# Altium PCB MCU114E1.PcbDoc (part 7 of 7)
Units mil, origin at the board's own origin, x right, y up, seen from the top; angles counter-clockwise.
Board outline 4163.97 x 2322.49 mil, 8 copper layers (Top Layer, GND 2, Signal Layer 3, Power 4, Power 5, Signal Layer 6, GND 7, Bottom), stack 61.2 mil thick; 444 components, 416 nets, 1812 pads, 989 vias.
Unrouted connection lines stored in the file: 3.
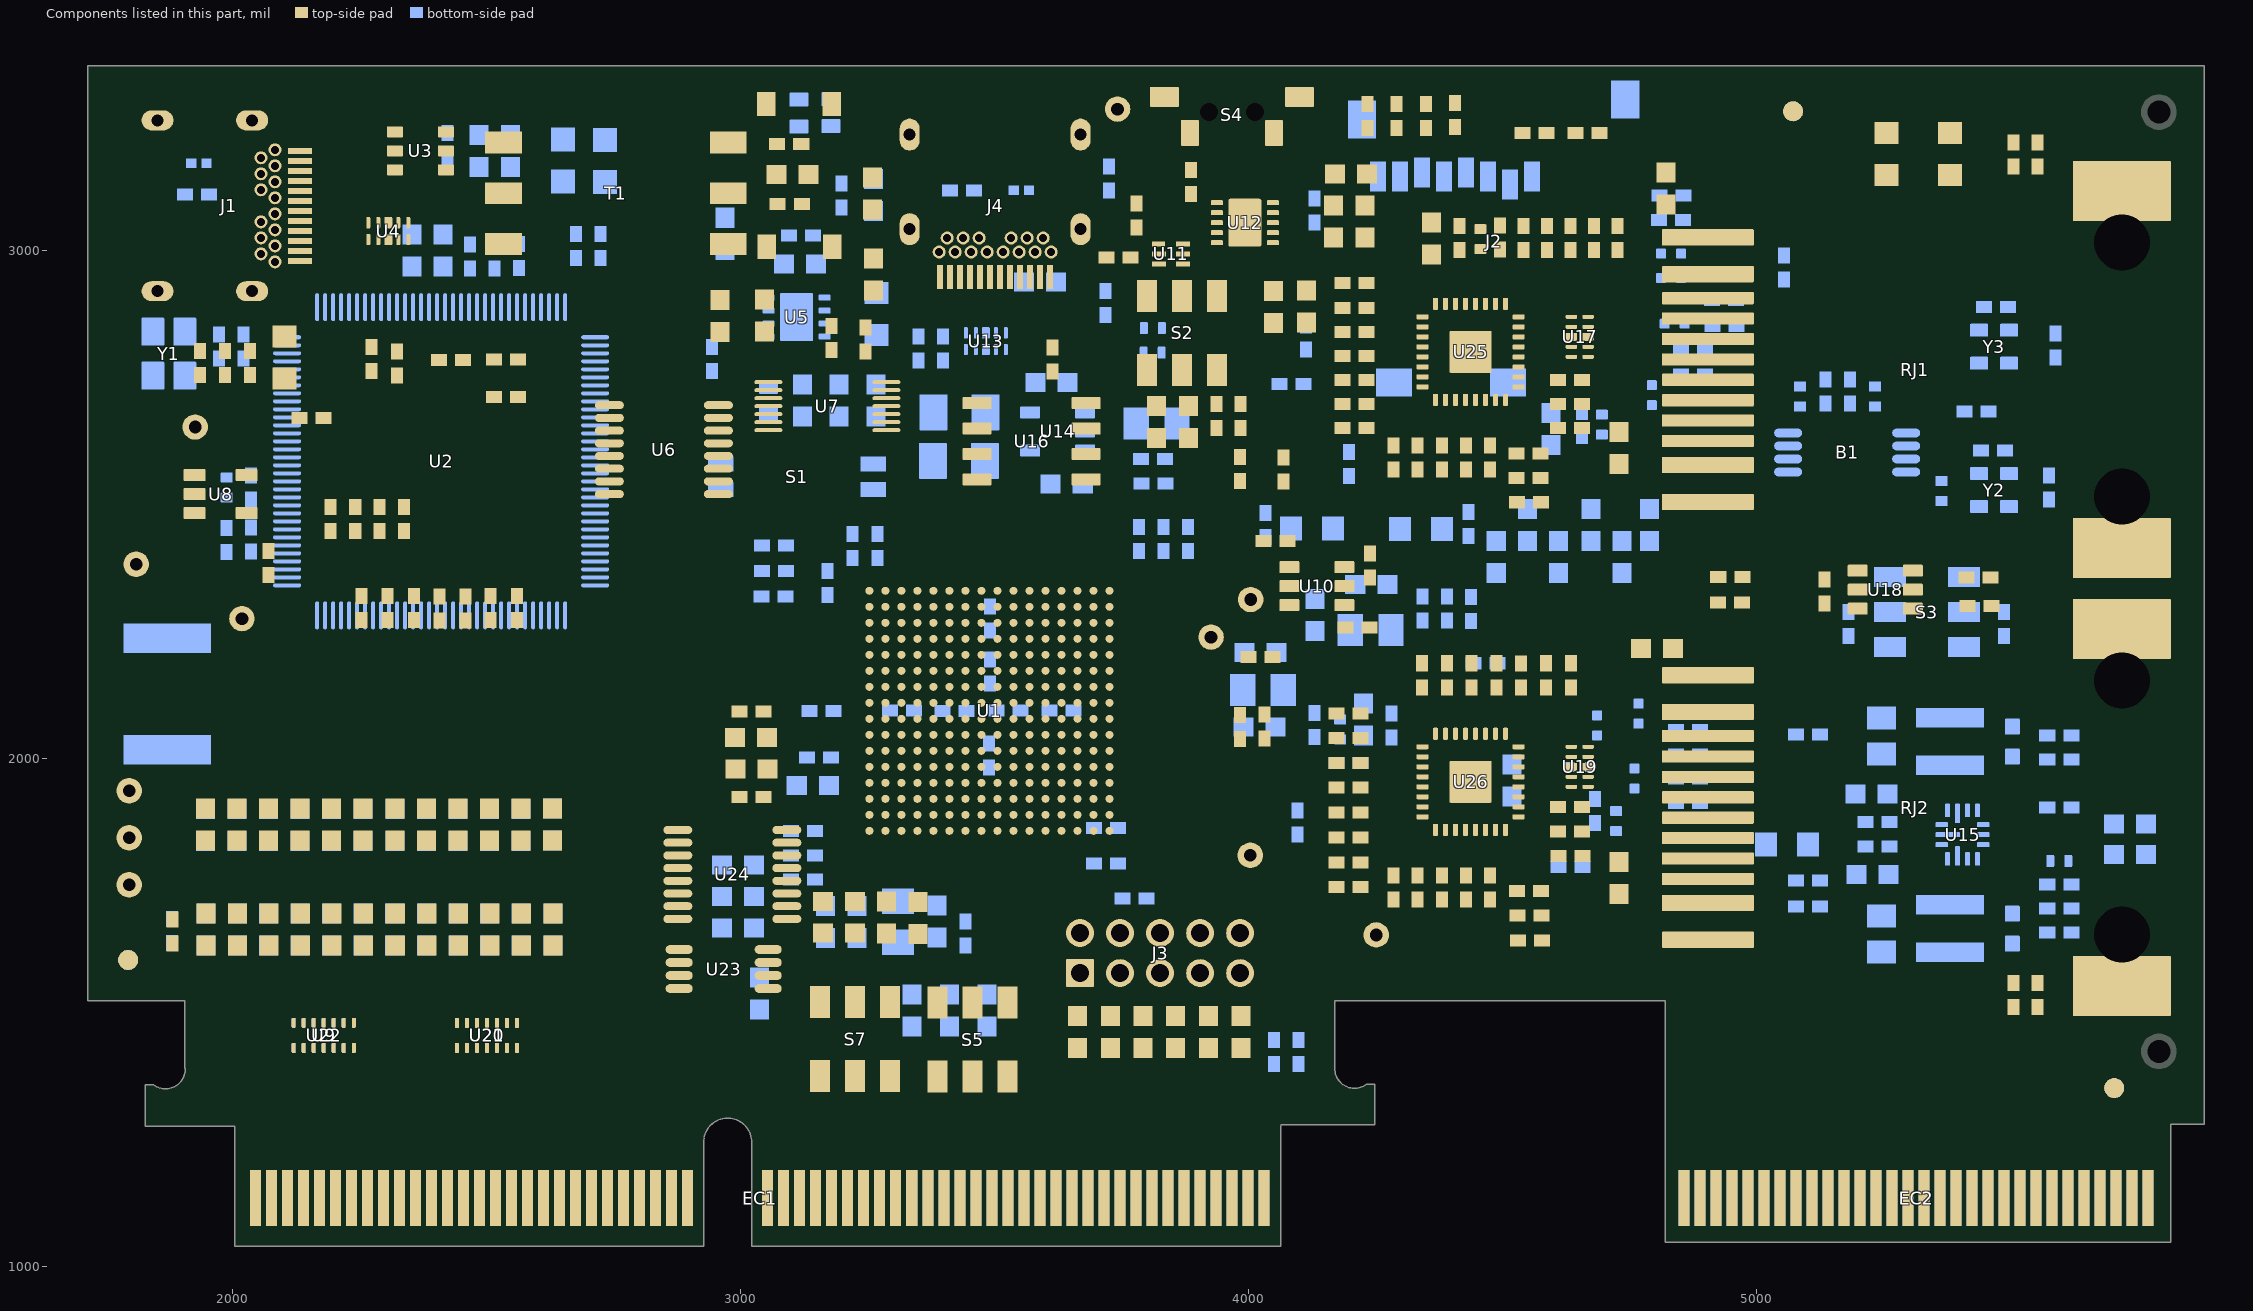
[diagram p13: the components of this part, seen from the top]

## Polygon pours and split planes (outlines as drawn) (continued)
NetC50_2 on Bottom "BOTTOM_NETC50_2_P194" (solid, remove dead copper, pour order 194): 5110,2069.34 5110,2013.68 5140.32,2013.68 5189.18,1964.82 5295.41,1964.82 5295.41,2025 5546,2025 5546,2058.05 5550.44,2062.5 5591.94,2062.5 5591.94,2028.87 5599.66,2028.87 5639.18,2028.87 5639.18,2106.82 5626,2120 5295.41,2120 5295.41,2054.66 5198.34,2054.66 5183.66,2069.34
NetL2_1 on Bottom "BOTTOM_NETL2_1_P219" (solid, remove dead copper, pour order 219): 5480,1958 5452.75,1958 5404.44,1909.69 5404.44,1871.16 5383.69,1871.16 5383.69,1932.72 5358.41,1958 5301,1958 5301,2026 5480,2026
NetL1_1 on Bottom "BOTTOM_NETL1_1_P222" (solid, remove dead copper, pour order 222): 5300,1744.71 5361.76,1744.71 5386,1768.96 5386,1828 5397.51,1828 5397.76,1828.24 5402.57,1823.43 5402.57,1788.43 5446.29,1744.71 5464,1744.71 5464,1676 5300,1676
5V0 on Bottom "BOTTOM_5V0_P225" (solid, remove dead copper, pour order 225): 5183.99,1801.23 5183.99,1844.5 5244,1844.5 5244,1820.73 5353.46,1820.73 5381.67,1820.73 5381.67,1764.63 5356.18,1739.14 5183.99,1739.14
5V0 on Bottom "BOTTOM_5V0_P229" (solid, remove dead copper, pour order 229): 5218.85,1959.23 5218.85,1896 5301,1896 5347,1896 5364.53,1878.47 5386.62,1878.47 5386.62,1946.38 5373.77,1959.23
5V0 on Bottom "BOTTOM_5V0_P230" (solid, remove dead copper, pour order 230): 5851.44,1971.69 5740.44,1971.69 5740.44,1851.69 5851.44,1851.69
EMU_USB_5V0 on Bottom "BOTTOM_EMU_USB_5V0_P231" (solid, remove dead copper, pour order 231): 2345.08,3216.85 2355.04,3216.85 2402.43,3216.85 2402.43,3207.9 2456.01,3207.9 2456.01,3189.27 2617.83,3189.27 2617.83,3074.27 2410.83,3074.27 2345.08,3140.02
5V0 on Bottom "BOTTOM_5V0_P232" (solid, remove dead copper, pour order 232): 3032.83,3339.27 3032.83,3271.27 3040.1,3264 3350,3264 3462.73,3151.27 3821.06,3151.27 3821.06,3339.27
EMU_3V3 on Bottom "BOTTOM_EMU_3V3_P234" (solid, remove dead copper, pour order 234): 2074.83,2690.27 2074.83,2542.27 1962.83,2542.27 1962.83,2690.27
EMU_GND on GND 2 "GND_2_EMU_GND_P206" (solid, remove dead copper, pour order 206): 1745.23,3346.77 2776.83,3346.77 2776.83,2365.27 2614.83,2203.27 1743.04,2203.27
ETH1_EARTH on GND 2 "GND_2_ETH1_EARTH_P172" (solid, remove dead copper, pour order 172): 5466,3228 5468,3230 5623,3230 5623,3332.84 5622.83,3333.01 5625.05,3335.23 5851.76,3335.23 5851.76,1337.49 5849.54,1335.27 5551.33,1335.27 5551.33,1598.1 5631.83,1598.1 5631.83,1728.84 5631.45,1729.22 5631.38,1729.16 4983.08,1729.16 4983.08,1806.03 5628.83,1806.03 5628.83,2186.78 5547.83,2267.78 5542.42,2267.78 5542.42,2430.79 5617.42,2505.79 5617.42,2593.86 5612.01,2599.27 4983.08,2599.27 4983.08,2696.27 5622.83,2696.27 5622.83,3075.27 5621.71,3074.15 5466.26,3074.15 5466.26,3229.26 5467,3230
GND on GND 2 "GND_2_GND_P227" (solid, remove dead copper, pour order 227): 1740.14,2050.63 1740.96,2051.46 2685.18,2051.46 2685.18,2053.82 2933.48,2302.12 2933.15,2302.46 2933.15,3360.09 5627.81,3355.97 5627.81,3074.15 5627.81,2694.47 4994.75,2694.47 4994.75,2597.93 5642.5,2597.93 5642.5,2517.86 5559.5,2434.86 5559.5,2266.44 5640.96,2184.98 5640.96,1817.39 5627.81,1804.23 4994.75,1804.23 4994.75,1727.82 5643.49,1727.82 5643.49,1593.18 5563.59,1593.18 5563.59,1545.84 5654.96,1454.47 5859.96,1454.47 5871.96,1442.47 5871.96,1304.47 5853.63,1286.13 5803.96,1286.13 5803.96,1061.47 4845.96,1061.47 4845.96,1504.75 4810.67,1540.04 4190.53,1540.04 4166.96,1516.47 4166.96,1366.47 4196.96,1336.47 4240.93,1336.47 4240.93,1286.13 4061.39,1286.13 4061.39,1055.47 3043.96,1055.47 3043.96,1260.36 3005.86,1298.47 2961.96,1298.47 2921.96,1258.47 2921.96,1062 2029.96,1061.47 2029.96,1280.49 1853.93,1280.49 1853.93,1309.44 1853.93,1340.47 1903.2,1340.47 1923.48,1360.75 1923.48,1540.04 1740.96,1538.47
EMU_GND on GND 7 "GND_7_EMU_GND_P189" (solid, remove dead copper, pour order 189): 1723.76,3352.27 2773.69,3352.27 2773.69,2361.12 2615.83,2203.27 1718.78,2203.27
GND on GND 7 "GND_7_GND_P223" (solid, remove dead copper, pour order 223): 1711.87,2049.75 2668.68,2049.75 2911.87,2292.93 2911.87,3339.75 5862.87,3339.75 5862.87,1399.27 5862.87,1283.27 5819.33,1283.27 5800.43,1264.37 5800.43,1034.29 4825.85,1034.29 4805.15,1054.99 4805.15,1508.27 4157.83,1508.27 4161.87,1504.23 4161.87,1363.27 4186.87,1343.27 4225.84,1343.27 4225.84,1274.29 4225.84,1264.37 4225.74,1264.27 4048.91,1264.27 4048.91,1030.29 4047.93,1031.27 3017.87,1031.27 3017.87,1243.12 2984.24,1276.75 2940.35,1276.75 2911.87,1248.27 2911.87,1042.27 2007.87,1042.27 2002.87,1037.27 2002.87,1269.27 1830.87,1269.27 1817.83,1282.31 1817.83,1342.27 1879.87,1342.27 1914.03,1376.43 1914.03,1535.75 1711.87,1535.75
VDDA_3V3 on Power 5 "POWER_5_VDDA_3V3_P176" (solid, remove dead copper, pour order 176): 1895.5,1554.5 1882,1568 1882,1949.33 1908.81,1976.14 2636.52,1976.14 2682.24,1930.41 2956.58,1930.41 2956.58,2068.27 3045.96,2157.65 3239.1,2157.65 3345.83,2050.92 3403.26,2050.92 3411.33,2042.86 3411.33,1987.27 3449.83,1948.77 3449.83,1911.66 3497.82,1863.66 3497.82,1649.78 3469.12,1621.08 3050.23,1621.08 3008.33,1579.17 3008.33,1292.33 2940.33,1292.33 2915.5,1267.5 2915.5,1063.5 2012.64,1063.5 2002.35,1073.79 2003.45,1074.89 2003.45,1280.06 1844.06,1280.06 1831.79,1292.33 1839.45,1299.99 1839.45,1350.61 1913.34,1350.61 1914.03,1351.3 1913.34,1550
VBUS_5V0 on Power 5 "POWER_5_VBUS_5V0_P207" (solid, remove dead copper, pour order 207): 3360.28,3165.77 3742.83,3165.77 3742.83,2775.28 3742.77,2775.34 3595.83,2775.34 3595.83,2695.9 3594.77,2694.83 3594.94,2694.66 3683.46,2694.66 3683.46,2516.61 3682.8,2517.27 3366.15,2517.27
ISO_Pout_5V0 on Power 5 "POWER_5_ISO_POUT_5V0_P218" (solid, remove dead copper, pour order 218): 2925.35,2938.68 3006.12,2938.68 3006.12,2816.64 3177.72,2816.64 3177.72,3106.79 3226.83,3155.9 3226.83,3332.27 2925.09,3332.27 2924.35,3333.01
EMU_3V3 on Power 5 "POWER_5_EMU_3V3_P228" (solid, remove dead copper, pour order 228): 1737.26,3345.27 2781.99,3345.27 2781.99,2369.43 2613.83,2201.27 1732.3,2201.27
3V3 on Power 5 "POWER_5_3V3_P246" (solid, remove dead copper, pour order 246): 1724.35,2052.27 2679.08,2052.27 2916.26,2300.45 2920.95,3363.27 5875.35,3363.27 5875.35,1422.79 5875.35,1306.79 5831.81,1306.79 5812.91,1287.89 5812.91,1057.81 4838.33,1057.81 4817.63,1078.51 4817.63,1531.79 4170.32,1531.79 4174.35,1527.75 4174.35,1386.79 4199.35,1366.79 4238.32,1366.79 4238.32,1297.81 4238.32,1287.89 4238.22,1287.79 4061.39,1287.79 4061.39,1053.81 4060.42,1054.79 3030.35,1054.79 3030.35,1266.64 2996.72,1300.27 2952.83,1300.27 2924.35,1271.79 2924.35,1060.79 2015.35,1060.79 2002.35,1073.79 2002.35,1292.79 1843.35,1292.79 1830.32,1305.83 1830.32,1365.79 1892.35,1365.79 1914.35,1387.79 1914.35,1541.79 1724.35,1541.79

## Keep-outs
Keep-Out Layer:
  text ".Layer_Name" at -765.05,-899.49 h60

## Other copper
Top Layer:
  pour cut-out: 3998.12,1341.27 4008,1331.39 4008,1330 4077,1399 4064,1412 4064,1407.15
  pour cut-out: 2035.26,1075.15 2897.18,1075.15 2897.18,1071.04 2035.26,1071.04
  pour cut-out: 3052.19,1075.15 4036.15,1075.15 4032.62,1071.62 4032.62,1071.04 3052.19,1071.04
  pour cut-out: 3816.28,1803 3823.96,1803 3824.37,1803.42 3916.79,1711 3912.19,1711 3902.4,1701.21 3815.51,1788.09 3815.51,1801.15
  pour cut-out: 3264.59,1929.58 3264.59,1924.78 3286.84,1902.53 3272.61,1888.29 3239.44,1888.29 3231.94,1895.78 3264.51,1928.35
  pour cut-out: 3390.41,1878.36 3422.28,1878.36 3426.45,1874.19 3420.14,1867.88 3420.14,1812.39 3399.98,1812.39 3390.41,1821.95
  pour cut-out: 3360.96,1947.64 3367.56,1947.64 3411.33,1947.64 3411.33,1873.75 3411.33,1878.36 3401.09,1878.36 3361.06,1878.36 3361.05,1887.28 3360.96,1942
  pour cut-out: 3476.63,2059.92 3482.38,2065.66 3503.01,2065.66 3503.01,1798.5 3496.8,1792.3 3494.41,1794.68 3479,1794.68 3479,1860.24 3462.72,1876.52 3460.39,1874.19 3434.05,1874.19 3434.05,1929.62 3467.44,1963.01 3467.44,2054.98 3472.38,2059.92
  pour cut-out: 3520.86,2107.12 3738.77,2107.12 3738.77,2086.67 3739.25,2086.19 3738.59,2085.52 3513.76,2085.52 3513.76,2100.03
  pour cut-out: 3471.51,2317.63 3508.13,2317.63 3508.13,2194.55 3502.35,2188.77 3502.11,2189.02 3442.82,2189.02 3442.82,2294.84 3467.34,2319.36
  pour cut-out: 2903,2732 2906.48,2728.52 2924.45,2728.52 2924.45,2541.46 2923.64,2540.66 2918.31,2546 2901,2546 2901,2730
  pour cut-out: 3894,2334 3900.17,2327.83 3945.77,2327.83 3945.77,2305.21 3931.83,2291.27 3928.06,2295.04 3854.17,2295.04 3854.17,2303.35 3885.86,2335.04
  text ".Layer_Name" at -733,-894 h60
Signal Layer 3:
  text ".Layer_Name" at -777.17,-912.73 h60
GND 2:
  text ".Layer_Name" at -742.17,-892.73 h60
GND 7:
  text ".Layer_Name" at -737.17,-889.73 h60
Signal Layer 6:
  text ".Layer_Name" at -725.17,-888.73 h60
Power 4:
  text ".Layer_Name" at -713.17,-903.73 h60
Power 5:
  text ".Layer_Name" at -737.17,-889.73 h60
Bottom:
  pour cut-out: 5368.98,1336.77 5372.08,1339.87 5388.48,1339.87 5388.48,1290.83 5390.44,1288.87 5381.76,1280.19 5371.77,1280.19 5371.77,1333.98
  pour cut-out: 5793,1238 5793,1196 5792.39,1195.39 5781.08,1195.39 5781.08,1228.92 5772,1238
  text ".Layer_Name" at -732.17,-905.73 h60

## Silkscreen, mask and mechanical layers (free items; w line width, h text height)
Top Overlay:
  text "-----------------------------" at 2900.19,3314.34 h35 r269.64
  text "---------------------------" at 2769.15,3308.34 h35 r269.64
  text "ETH1_EARTH" at 5508,3277.1 h40
  text "5V0" at 3716,3215.44 h40
  text "P0" at 4979,3161.78 h65
  text "XRSn" at 4008,3158.44 h40
  text "1" at 3982,2934.27 h40
  text "0" at 3735,2904.94 h40
  text "SEL 1" at 3651.49,2865.05 h40
  text "SEL 2" at 3651.49,2789.12 h40
  text "0" at 3730,2739.44 h40
  text "1" at 3983.6,2733.42 h40
  text "EMU_5V0" at 1951.54,2609.96 h40
  text "EMU_3V3" at 1754.67,2424.69 h40
  text "VDD_1V2" at 3805.04,2301.1 h40
  text "XRSn" at 3799,2226.44 h40
  text "EMU_GND" at 1928.9,2214.53 h40
  text "Cold Side" at 2619.69,2210.52 h55 r47.05
  text "-------" at 2626.55,2182.98 h35 r45.17
  text "------------------------" at 1772.83,2176.77 h35
  text "Hot Side" at 2772.82,2089.6 h55 r45.91
  text "----------" at 2688.55,2044.71 h35 r46.53
  text "--------------------------" at 1770.09,2037.49 h35
  text "HSEC_5V0" at 1728,1880.1 h40
  text "VDDIO_3V3" at 3768.34,1801.17 h40
  text "GND" at 1763.85,1788.79 h35
  text "3V3" at 1760,1695.44 h40
  text "ERRORSTS" at 4022,1637.44 h40
  text "SEL 1" at 3411.36,1564.69 h40
  text "SEL 2" at 3180.51,1560.71 h40
  text "1" at 3129,1559 h40
  text "0" at 3318.8,1558.4 h40
  text "0" at 3354.18,1558.29 h40
  text "1" at 3543,1558 h40
  text "Ext Vref" at 2978.27,1486.61 h40
  text "P1" at 4985.61,1482 h65
  text "ETH1_EARTH" at 5515,1415.1 h40
  text "1" at 3121,1310 h40
  text "0" at 3311.26,1309.38 h40
  text "0" at 3354.75,1308.61 h40
  text "SEL 1" at 3185.83,1307.93 h40
  text "SEL 2" at 3400,1304.44 h40
  text "1" at 3537.83,1304.45 h40
  text "55" at 2880,1280.94 h40
  text "57" at 3039,1280.94 h40
  text "119" at 3994,1280.71 h40
  text "121" at 4831,1280.71 h40
  text "179" at 5739,1280.71 h40
  text "1" at 2029.96,1280.49 h40
  text ".Layer_Name" at -752.17,-886.73 h60
Bottom Overlay:
  region: 4512,1714 4367,1714 4367,1649 4512,1649
  text "-----------------------------" at 2900.19,3314.34 h35 r269.64
  text "---------------------------" at 2769.15,3308.34 h35 r269.64
  text "0" at 2926.6,2621.15 h40
  text "1" at 3300,2602 h40
  text "SEL 1" at 3307.67,2569.14 h40 r270
  text "1" at 3298.95,2474.95 h40
  text "SEL 2" at 3308.77,2465.55 h40 r270
  text "0" at 2933,2464.44 h40
  text "1" at 5217.79,2389.18 h40
  text "1" at 5462.68,2383.61 h40
  text "SEL 2" at 5185,2370.44 h40
  text "SEL 1" at 5575,2367.44 h40
  text "-------" at 2626.55,2182.98 h35 r45.17
  text "0" at 5203.35,2176.87 h40
  text "------------------------" at 1771.83,2175.77 h35
  text "0" at 5447.95,2173.86 h40
  text "----------" at 2688.54,2044.71 h35 r46.5
  text "--------------------------" at 1770.09,2037.49 h35
  text "'.PRJ_Number'.PCB_Rev-" at 4814.67,1664.88 h60
  text "C2000 F28P65x controlCARD" at 5030,1595 h60
  text "2" at 2046.62,1282.29 h40
  text "56" at 2917,1281 h40
  text "58" at 3064.19,1281.3 h40
  text "120" at 4049,1281 h40
  text "122" at 4887.35,1279.94 h40
  text "180" at 5794,1280 h40
  text ".Layer_Name" at -750.17,-896.73 h60
Top Paste:
  text ".Layer_Name" at -765.05,-899.49 h60
Bottom Paste:
  text ".Layer_Name" at -765.05,-899.49 h60
Top Solder:
  rectangle: 4817,1044.63 5817,1241
  rectangle: 2002.01,1032 2932,1238.09
  rectangle: 3017.87,1035 4075,1241
  text ".Layer_Name" at -765.05,-899.49 h60
  text ".Layer_Name" at -765.05,-899.49 h60
Bottom Solder:
  rectangle: 4816,1037.81 5817,1240
  rectangle: 2002,1040.78 2927.44,1240.39
  rectangle: 3022.33,1040.78 4069,1239.79
  text ".Layer_Name" at -765.05,-899.49 h60
Drill Guide:
  text ".Layer_Name" at -765.05,-899.49 h60
M1 Board Outline:
  lines w10: 1906.8,1391.27 1906.8,1524.27 1715.83,1524.27 1715.83,3363.27 5877.8,3363.27 ; 1907.3,1391.29 cw(c1868.35,1389.36) 1844.8,1358.27 1828.8,1358.27 1828.8,1277 2005,1277 2005,1045.98 ; 2010.84,1041.04 2922.46,1041.04 ; 2927.26,1047.48 2927.26,1241.96 ; 2927.36,1242.93 cw(c2974.85,1242.55) 3022.33,1242.93 3022.33,1045.77 ; 3027.41,1040.69 4070.11,1040.76 ; 4070.11,1046.6 4070.11,1276.93 ; 4070.11,1280.27 4247.8,1280.27 4247.8,1359.27 4231.8,1359.27 cw(c4208.3,1390.39) 4169.3,1390.27 ; 4168.8,1390.27 4168.8,1487.86 4168.8,1524.27 4819.11,1524.27 4819.11,1048.27 5814.39,1048.27 5814.39,1280.37 5879.8,1280.37 5879.8,3363.27
  text ".Layer_Name" at -765.05,-899.49 h60
M2 Board Dimensions:
  rectangle: -1342.05,-315.99 -1217.05,-190.99
  rectangle: -1217.05,-440.99 -842.05,-315.99
  lines w5: 1998.81,1311.29 2008.81,1301.29 ; 2018.81,1311.29 2008.81,1301.29 ; 2178.81,1346.29 2033.81,1346.29 2008.81,1321.29 2008.81,1301.29 ; 4088.81,1251.29 4088.81,1266.29 ; 4103.81,1266.29 4088.81,1266.29 ; 4103.81,1561.29 4103.81,1526.29 4123.81,1526.29 4153.81,1526.29 ; 4143.81,1516.29 4153.81,1526.29 ; 4143.81,1536.29 4153.81,1526.29 ; 4338.81,1576.29 4348.81,1566.29 4823.81,1566.29 4823.81,1546.29 4823.81,1531.29 ; 4473.81,691.29 4473.81,861.29 4118.81,1216.29 4118.81,1236.29 4088.81,1266.29 ; 4813.81,1541.29 4823.81,1531.29 ; 4833.81,1541.29 4823.81,1531.29 ; 5778.81,1396.29 5778.81,1371.29 5798.81,1351.29 5818.81,1331.29 5818.81,1316.29 5818.81,1291.29 ; 5808.81,1301.29 5818.81,1291.29 ; 5828.81,1301.29 5818.81,1291.29
  lines w7: -1342.05,-315.99 -342.05,-315.99 ; -1217.05,-440.99 -1217.05,-190.99 ; -1092.05,-440.99 -1092.05,-190.99 ; -842.05,-440.99 -842.05,-190.99 ; -592.05,-440.99 -592.05,-190.99 ; -1342.05,-440.99 -342.05,-440.99 -342.05,-190.99 -1342.05,-190.99 -1342.05,-440.99
  lines w10: 1923.81,1566.29 1923.81,1546.29 ; 1943.81,1546.29 1923.81,1546.29 ; 2018.81,1561.29 1938.81,1561.29 1923.81,1546.29 ; 8495.95,186.01 8563.95,186.01 ; 8537.95,157.01 8564.95,185.01 ; 8537.95,216.01 8564.95,186.01 ; 8571.95,1531.01 8639.95,1613.01 ; 8573.95,139.01 8573.95,461.01 ; 8573.95,502.01 8623.95,448.01 8733.95,448.01 8780.95,505.01 ; 8573.95,504.01 8573.95,1534.01 ; 8638.95,1614.01 8702.95,1527.01 ; 8656.95,354.01 8724.95,354.01 ; 8698.95,325.01 8725.95,353.01 ; 8698.95,384.01 8725.95,354.01 ; 8703.95,1526.01 8775.95,1616.01 ; 8734.95,139.01 8734.95,421.01 ; 8780.95,504.01 8780.95,1534.01 8780.95,1619.01 ; 8781.95,139.01 8781.95,461.01 ; 8787.92,1154.63 cw(c8731.95,447.01) 9171.29,1004.54 ; 8789.8,1153.26 ccw(c8929.55,1387.92) 8840.67,1129.67 ; 8789.95,189.01 8816.95,159.01 ; 8789.95,190.01 8816.95,218.01 ; 8789.95,1160.01 cw(c8822.4,986.03) 8852.67,1160.4 ; 8791.95,190.01 8859.95,190.01 ; 8791.95,353.01 8818.95,323.01 ; 8791.95,354.01 8818.95,382.01 ; 8793.95,354.01 8861.95,354.01 ; 8807.95,543.01 9270.95,1115.01 ; 9117.95,1019.01 ccw(c9255.48,1359.44) 9172.61,1001.75 ; 9135.2,1052.31 cw(c9018.34,918.86) 9173.95,1004
  text "X2" at 4228.81,1681.29 h60
  text "R 39.00" at 4004.83,1593.27 h60
  text "R 39.00" at 2048.81,1541.29 h60
  text "R 39.00" at 5458.81,1416.29 h60
  text "R 39.00" at 2208.81,1311.29 h60
  text "30" at 8976.95,1175.01 h60
  text "R 39.00" at 4343.81,606.29 h60
  text "18MIL" at 8902.95,326.01 h60
  text "62MIL" at 8895.95,162.01 h60
  text "GOLD FINGER" at 8414.95,-74.99 h60
  text "SIDE VIEW" at 8468.95,-187.99 h60
  text ".Layer_Name" at -765.05,-899.49 h60
M3 3D STEP Top:
  text ".Layer_Name" at -765.05,-899.49 h60
M4 3D STEP Bottom:
  text ".Layer_Name" at -765.05,-899.49 h60
M5 Assembly Top:
  lines w10: -1634.05,-971.16 4965.95,-971.16 ; -1634.05,-767.83 4967.95,-767.83 ; -1634.05,-564.49 -1634.05,-1174.49 2370.95,-1174.49 4967.95,-1174.49 4967.95,-564.5 -1633.55,-564.5 -1633.55,-1174.49 -58.05,-1174.49 ; 830.95,-1174.49 830.95,-564.5 ; 2097.95,-767.83 2097.95,-564.5 ; 2937.95,-767.83 2937.95,-564.5 ; 3559.95,-1180.99 3559.95,-978.16
  text "COMPONENTS MARKED 'DNP' SHOULD NOT BE POPULATED." at -188.55,-359.49 h60
  text "ASSEMBLY VARIANT:" at -189.05,-474.99 h60
  text ".VariantName" at 846.95,-474.99 h60
  text "PCB VIEWED FROM TOP SIDE" at -1570.55,-696.66 h60
  text "BOARD #:" at 905.95,-696.66 h60
  text ".PRJ_Number" at 1451.45,-696.66 h60
  text "REV:" at 2295.95,-696.66 h60
  text ".PCB_Rev" at 2587.45,-696.66 h60
  text "SVN REV:" at 3133.95,-696.66 h60
  text "TID #:" at 905.95,-899.99 h60
  text ".TID" at 1451.45,-899.99 h60
  text "PLOT NAME =" at -1570.55,-1105.33 h60
  text ".plot_File_Name" at -765.05,-1105.33 h60
  text "GENERATED    :" at 907.95,-1105.33 h60
  text ".Print_Date" at 1777.45,-1105.33 h60
  text ".Print_Time" at 2506.45,-1105.33 h60
  text "TEXAS INSTRUMENTS" at 3770.95,-1105.33 h60
M6 Assembly Bottom:
  lines w10: -1634.55,-768.33 4967.45,-768.33 ; -1632.55,-971.66 4967.45,-971.66 ; -226.55,-1181.49 -226.55,-978.66 ; 395.45,-768.33 395.45,-565 ; 1235.45,-768.33 1235.45,-565 ; 2502.45,-1174.99 2502.45,-565 ; 3391.45,-1174.99 4966.95,-1174.99 4966.95,-564.99 -1634.55,-565 -1634.55,-1174.99 962.45,-1174.99 4967.45,-1174.99 4967.45,-564.99
  text "COMPONENTS MARKED 'DNP' SHOULD NOT BE POPULATED." at 4759.95,-358.99 h60
  text ".VariantName" at 3715.95,-474.99 h60
  text "ASSEMBLY VARIANT:" at 4754.95,-474.99 h60
  text "SVN REV:" at 199.45,-697.16 h60
  text ".PCB_Rev" at 745.95,-697.16 h60
  text "REV:" at 1037.45,-697.16 h60
  text ".PRJ_Number" at 1881.95,-697.16 h60
  text "BOARD #:" at 2427.45,-697.16 h60
  text ".TID" at 1881.95,-900.49 h60
  text "TID #:" at 2427.45,-900.49 h60
  text "TEXAS INSTRUMENTS" at -437.55,-1105.83 h60
  text ".Print_Time" at 826.95,-1105.83 h60
  text ".Print_Date" at 1555.95,-1105.83 h60
  text "GENERATED    :" at 2425.45,-1105.83 h60
  text ".plot_File_Name" at 4098.45,-1105.83 h60
  text "PLOT NAME =" at 4903.95,-1105.83 h60
M9 Title Sheet:
  drawing of 57 lines, arcs and shapes, not listed
  text "1" at -602.21,7995.51 h70
  text "2" at 1893.45,7995.51 h70
  text "3" at 4382.79,7995.51 h70
  text "4" at 6889.46,7995.51 h70
  text "5" at 9388.45,7995.51 h70
  text "6" at 11893.45,7995.51 h70
  text "A" at -1758.55,6852.51 h70
  text "A" at 13041.45,6852.51 h70
  text "B" at -1758.55,4472.51 h70
  text "B" at 13041.45,4472.51 h70
  text "C" at -1758.55,2097.51 h70
  text "C" at 13041.45,2097.51 h70
  text "PROJECT TITLE:" at 10001.45,236.51 h45
  text ".PRJ_Title" at 10051.45,103.18 h70
  text "DESIGNED FOR:" at 10001.45,-64.49 h45
  text ".PRJ_Customer" at 10051.45,-204.49 h70
  text "D" at -1758.55,-272.49 h70
  text "D" at 13041.45,-272.49 h70
  text "FILE NAME:" at 10001.45,-364.49 h45
  text ".PCB_File_Name_No_Path" at 10051.45,-484.49 h70
  text "Texas Instruments (TI) and/or its licensors do not warrant the accuracy or completeness of this specification" at 5031.95,-646.33 h45
  text "ENGINEER:" at 10001.45,-654.49 h45
  text "LAYOUT BY:" at 11506.45,-654.49 h45
  text "or any information contained therein. TI and/or its licensors do not warrant that this design will meet" at 4986.97,-759 h45
  text ".PRJ_Engineer" at 10051.45,-809.49 h70
  text ".PCB_Layout" at 11556.95,-809.49 h70
  text "the specifications, will be suitable for your application or fit for any particular purpose, or will operate in" at 4986.97,-871.66 h45
  text ".Layer_Name" at -765.05,-899.49 h60
  text "ALTIUM DESIGNER VERSION:" at 11506.45,-964.49 h45
  text "an implementation. TI and/or its licensors do not warrant that the design is production worthy. You should" at 4986.97,-984.33 h45
  text "completely validate and test your design implementation to confirm the system functionality for your application." at 5031.95,-1096.99 h45
  text ".print_Scale" at 10051.45,-1097.82 h70
  text ".Application_BuildNumber" at 11556.95,-1097.82 h70
  text "1" at -602.21,-1304.49 h70
  text "2" at 1893.45,-1304.49 h70
  text "3" at 4382.79,-1304.49 h70
  text "4" at 6889.46,-1304.49 h70
  text "5" at 9388.45,-1304.49 h70
  text "6" at 11893.45,-1304.49 h70
M10 Fab Notes:
  drawing of 185 lines, arcs and shapes, not listed
  text "DESIGN INFORMATION" at 11039.97,6455.18 h60
  text "5" at 11493.81,6326.29 h60
  text "MIN. TRACK WIDTH:" at 10395.41,6323.05 h60
  text "MIL" at 11646.41,6323.05 h60
  text "4" at 11503.81,6206.29 h60
  text "MIN. CLEARANCE:" at 10395.41,6198.93 h60
  text "MIL" at 11646.41,6198.93 h60
  text "MIN. VIA PAD SIZE:" at 10395.41,6074.8 h60
  text "18" at 11461.66,6074.8 h60
  text "MIL" at 11646.41,6074.8 h60
  text "0.05mm (2MIL)" at 11090.41,5944.9 h60
  text "MINIMUM ANNULAR RING" at 10066.18,5936.68 h60
  text "EXTERNAL" at 11798.41,5936.68 h60
  text "PER" at 10266.18,5826.55 h60
  text "IPC-D-275 CLASS 2 LEVEL C" at 10486.18,5826.55 h60
  text "MIL, HOLES" at 11974.41,5726.07 h60
  text "+/-" at 11581.95,5717.49 h60
  text "+/-" at 12435.95,5717.49 h60
  text "REGISTRATION TOLERANCES:" at 10066.18,5716.42 h60
  text "METAL" at 11265.95,5716.42 h60
  text "5" at 11842.15,5716.43 h60
  text "3" at 12675.15,5716.43 h60
  text "MIL" at 12791.41,5716.42 h60
  text "HOLE SIZE TOLERANCE (UNLESS OTHERWISE SPECIFIED):" at 10066.18,5618.11 h60
  text "+/-" at 12435.95,5615.24 h60
  text "3" at 12675.15,5614.17 h60
  text "MIL" at 12791.41,5614.17 h60
  text "MATERIAL:" at 9991.41,5476.52 h60
  text "FR-4 High Tg" at 10977.85,5348 h60
  text "X" at 10833.41,5340.01 h60
  text "FR-408" at 10412.41,5335.49 h60
  text "OTHER" at 11900.41,5335.49 h60
  text "62 MIL (1.57mm) +/-10%" at 10732.51,5192.46 h60
  text "X" at 10612.41,5190.01 h60
  text "THICKNESS:" at 10066.18,5184.24 h60
  text "OTHER" at 12017.41,5184.24 h60
  text "TOLERANCE:" at 10066.18,5045.93 h60
  text "X" at 10914.41,5045.93 h60
  text "ANSI IPC-6012 TYPE 3 CLASS 2" at 11092.43,5045.93 h60
  text "OTHER +/-" at 11092.41,4901.74 h60
  text "BOW & TWIST:" at 10066.18,4756.55 h60
  text "X" at 10914.41,4756.55 h60
  text "ANSI IPC-6012 TYPE 3 CLASS 2" at 11092.43,4756.55 h60
  text "OTHER +/-" at 11092.41,4609.85 h60
  text "DRILLING:" at 9991.41,4479.23 h60
  text "NC_DRILL FILES" at 11752.41,4374.05 h60
  text "REFERENCE:" at 10066.18,4370.11 h60
  text "X" at 10723.41,4370.01 h60
  text "AS SHOWN" at 10901.41,4370.11 h60
  text "X" at 11624.41,4370.11 h60
  text "OTHER" at 12050.41,4227.86 h60
  text "PTH COPPER THICKNESS:" at 10065.86,4224.33 h60
  text "X" at 11205.09,4224.33 h60
  text "20-30 um" at 11333.09,4224.33 h60
  text "BOARD FINISH:" at 9991.41,4076.73 h60
  text "SILKSCREEN:" at 10146.63,3966.6 h60
  text "X" at 11104.41,3966.6 h60
  text "TOP" at 11221.41,3966.6 h60
  text "X" at 11614.41,3966.6 h60
  text "BOTTOM" at 11732.41,3966.6 h60
  text "SILKSCREEN COLOR:" at 10146.63,3811.42 h60
  text "X" at 11103.41,3811.42 h60
  text "WHITE" at 11221.41,3811.42 h60
  text "OTHER" at 11732.41,3811.42 h60
  text "BLUE" at 12387.41,3677.97 h60
  text "GREEN" at 11352.41,3667.97 h60
  text "X" at 11824.41,3667.97 h60
  text "OTHER" at 11970.41,3667.97 h60
  text "SOLDER RESIST COLOR:" at 10146.63,3661.1 h60
  text "X" at 11824.81,3515.99 h60
  text "MATTE" at 11352.41,3513.72 h60
  text "SEMI-GLOSS" at 11969.95,3513.08 h60
  text "IMMERSION GOLD (ENIG)" at 11052.41,3340.94 h60
  text "ENEPIG" at 12389.95,3333.72 h60
  text "SURFACE FINISH:" at 9991.41,3332.72 h60
  text "X" at 10874.41,3332.72 h60
  text "IMM. TIN/SILVER OR EQUIV" at 10320.95,3195.41 h60
  text "HARD GOLD OVER NICKEL 30u/80u, ON EDGEFINGERS" at 10695.37,3042.4 h60
  text "X" at 10164.41,3032.72 h60
  text "OTHER" at 10342.41,3031.47 h60
  text "ARRAY/PANEL:" at 9991.41,2896.09 h60
  text "CUT AND TRIM PER M1 BOARD OUTLINE" at 11052.41,2887.87 h60
  text "N.C. ROUTE" at 11052.41,2751.9 h60
  text "X" at 11740.41,2751.9 h60
  text "V. SCORE" at 11918.41,2751.9 h60
  text "CERTIFICATION:" at 9991.41,2622.78 h60
  text "MATERIALS AND WORKMANSHIP FOR ALL PCBS" at 10716.41,2622.78 h60
  text "TO MEET OR EXCEED THE REQUIREMENTS OF:" at 10716.41,2528.71 h60
  text "X" at 10353.92,2400.09 h60
  text "ANSI IPC-A-600F CLASS ->" at 10481.91,2400.09 h60
  text "X" at 12129.92,2400.09 h60
  text "2" at 12239.91,2400.09 h60
  text "1" at 11924.91,2398.59 h60
  text "3" at 12593.91,2398.59 h60
  text "RJ1 and RJ2 : NPTH on SMT pads are intentional per manufacturers footprint.  SMT pad copper may be pulled back 5-8Mil from holes as needed for processing." at 6879,2297 h59
  text "X" at 11165.92,2252.4 h60
  text "RoHS" at 11293.91,2252.4 h60
  text "OTHER" at 11938.32,2252.4 h60
  text "PER ORDER" at 12335.37,2252.4 h60
  text "ALL BOARDS MUST MEET OR EXCEED UL94-V0 REQUIREMENTS." at 10018.95,2098.57 h60
  text "PCB MUST BEAR THE UL94V-0 UL REGISTERED MATERIAL ID NUMBER" at 10018.95,1982.51 h60
  text "ADDITIONAL REQUIREMENTS:" at 9991.41,1813.08 h60
  text "REQUIRED" at 11773.41,1691.63 h60
  text "BARE BOARD ELEC. TEST:" at 10006.18,1688.77 h60
  text "NONE" at 11311.91,1688.77 h60
  text "X" at 12247.95,1689.01 h60
  text "PER ORDER" at 12365.41,1688.77 h60
  text "X" at 10062,1441 h60
  text "ALL LAYERS 6.1 MIL WIDE, 6 MIL SPACE / TRACES REQUIRE 90 OHM DIFFERENTIAL IMPEDANCE" at 10267,1378 h60
  text "X" at 10064.92,1241.09 h60
  text "ALL LAYERS 4.9 MIL WIDE, 6 MIL SPACE / TRACES REQUIRE 50 OHM DIFFERENTIAL IMPEDANCE" at 10182,1191 h60
  text "X" at 10068.92,1045.09 h60
  text "OUTER LAYERS 6.2 MIL WIDE, 6 MIL SPACE / TRACES REQUIRE 100 OHM DIFFERENTIAL IMPEDANCE" at 10190,997 h60
  text "X" at 10070.92,880.09 h60
  text "ALL LAYERS 5.2 MIL WIDE, 6 MIL SPACE / TRACES REQUIRE 50 OHM SE  IMPEDANCE MATCHING" at 10261,825 h60
  text ".Layer_Name" at -765.05,-899.49 h60
M11 Gerber Information:
  lines w10: -1634.05,-971.16 4965.95,-971.16 ; -1634.05,-767.83 4967.95,-767.83 ; -1634.05,-564.49 -1634.05,-1174.49 2370.95,-1174.49 4967.95,-1174.49 4967.95,-564.5 -1633.55,-564.5 -1633.55,-1174.49 -58.05,-1174.49 ; 830.95,-1174.49 830.95,-564.5 ; 2097.95,-767.83 2097.95,-564.5 ; 2937.95,-767.83 2937.95,-564.5 ; 3559.95,-1180.99 3559.95,-978.16
  text "ALL ARTWORK VIEWED FROM TOP SIDE" at -1570.55,-696.66 h60
  text "BOARD #:" at 905.95,-696.66 h60
  text ".PRJ_Number" at 1451.45,-696.66 h60
  text "REV:" at 2295.95,-696.66 h60
  text ".PCB_Rev" at 2587.45,-696.66 h60
  text "SVN REV:" at 3133.95,-696.66 h60
  text "LAYER NAME =" at -1570.55,-899.49 h60
  text "TID #:" at 905.95,-899.99 h60
  text ".TID" at 1451.45,-899.99 h60
  text "PLOT NAME =" at -1570.55,-1105.33 h60
  text ".plot_File_Name" at -765.05,-1105.33 h60
  text "GENERATED    :" at 907.95,-1105.33 h60
  text ".Print_Date" at 1777.45,-1105.33 h60
  text ".Print_Time" at 2506.45,-1105.33 h60
  text "TEXAS INSTRUMENTS" at 3770.95,-1105.33 h60
M12 Stackup:
  drawing of 503 lines, arcs and shapes, not listed
  text "Layer" at 5321.35,6821 h60
  text "Name" at 5731.26,6821 h60
  text "Material" at 6671,6821 h60
  text "Thickness" at 7530.77,6821 h60
  text "Constant" at 8180.6,6821 h60
  text "Board Layer Stack" at 8750.46,6821 h60
  text "Top Overlay" at 5731.26,6701 h60
  text "Top Solder" at 5731.26,6581 h60
  text "Solder Resist" at 6671,6581 h60
  text "0.50mil" at 7530.77,6581 h60
  text "3.6" at 8180.6,6581 h60
  text "1" at 5321.35,6461 h60
  text "Top Layer" at 5731.26,6461 h60
  text "CF-004" at 6671,6461 h60
  text "1.40mil" at 7530.77,6461 h60
  text "Dielectric 1" at 5731.26,6341 h60
  text "FR-4" at 6671,6341 h60
  text "5.00mil" at 7530.77,6341 h60
  text "3.7" at 8180.6,6341 h60
  text "2" at 5321.35,6221 h60
  text "GND 2" at 5731.26,6221 h60
  text "CF-004" at 6671,6221 h60
  text "1.40mil" at 7530.77,6221 h60
  text "Dielectric 2" at 5731.26,6101 h60
  text "FR-4" at 6671,6101 h60
  text "10.00mil" at 7530.77,6101 h60
  text "3.7" at 8180.6,6101 h60
  text "3" at 5321.35,5981 h60
  text "Signal Layer 3" at 5731.26,5981 h60
  text "CF-004" at 6671,5981 h60
  text "1.40mil" at 7530.77,5981 h60
  text "Dielectric 3" at 5731.26,5861 h60
  text "FR-4" at 6671,5861 h60
  text "5.00mil" at 7530.77,5861 h60
  text "3.7" at 8180.6,5861 h60
  text "4" at 5321.35,5741 h60
  text "Power 4" at 5731.26,5741 h60
  text "CF-004" at 6671,5741 h60
  text "1.40mil" at 7530.77,5741 h60
  text "Dielectric 4" at 5731.26,5621 h60
  text "FR-4" at 6671,5621 h60
  text "10.00mil" at 7530.77,5621 h60
  text "3.7" at 8180.6,5621 h60
  text "5" at 5321.35,5501 h60
  text "Power 5" at 5731.26,5501 h60
  text "CF-004" at 6671,5501 h60
  text "1.40mil" at 7530.77,5501 h60
  text "Dielectric 5" at 5731.26,5381 h60
  text "FR-4" at 6671,5381 h60
  text "5.00mil" at 7530.77,5381 h60
  text "3.7" at 8180.6,5381 h60
  text "6" at 5321.35,5261 h60
  text "Signal Layer 6" at 5731.26,5261 h60
  text "CF-004" at 6671,5261 h60
  text "1.40mil" at 7530.77,5261 h60
  text "Dielectric 6" at 5731.26,5141 h60
  text "FR-4" at 6671,5141 h60
  text "10.00mil" at 7530.77,5141 h60
  text "3.7" at 8180.6,5141 h60
  text "7" at 5321.35,5021 h60
  text "GND 7" at 5731.26,5021 h60
  text "CF-004" at 6671,5021 h60
  text "1.40mil" at 7530.77,5021 h60
  text "Dielectric 7" at 5731.26,4901 h60
  text "FR-4" at 6671,4901 h60
  text "5.00mil" at 7530.77,4901 h60
  text "3.7" at 8180.6,4901 h60
  text "8" at 5321.35,4781 h60
  text "Bottom" at 5731.26,4781 h60
  text "CF-004" at 6671,4781 h60
  text "1.40mil" at 7530.77,4781 h60
  text "Bottom Solder" at 5731.26,4661 h60
  text "Solder Resist" at 6671,4661 h60
  text "0.50mil" at 7530.77,4661 h60
  text "3.6" at 8180.6,4661 h60
  text "Bottom Overlay" at 5731.26,4541 h60
  text ".Layer_Name" at -765.05,-899.49 h60
M13 Component Bodies Top:
  text ".Layer_Name" at -765.05,-899.49 h60
M14 Component Bodies Bottom:
  text ".Layer_Name" at -765.05,-899.49 h60
M15 Courtyards Top:
  text ".Layer_Name" at -765.05,-899.49 h60
M16 Courtyards Bottom:
  text ".Layer_Name" at -765.05,-899.49 h60
Drill Drawing:
  circle w10: c-1197.12,5902.33 r33.33
  circle w10: c-1197.12,5302.33 r20
  circle w10: c-1197.12,5302.33 r33.33
  lines w10: -1230.45,5135.67 -1213.79,5135.67 -1213.79,5119 -1180.45,5119 -1180.45,5135.67 -1163.79,5135.67 -1163.79,5169 -1180.45,5169 -1180.45,5185.67 -1213.79,5185.67 -1213.79,5169 -1230.45,5169 -1230.45,5135.67 ; -1230.45,5435.67 -1213.79,5435.67 -1197.12,5419 -1180.45,5435.67 -1163.79,5435.67 -1180.45,5452.33 -1163.79,5469 -1180.45,5469 -1197.12,5485.67 -1213.79,5469 -1230.45,5469 -1213.79,5452.33 -1230.45,5435.67 ; -1230.45,5569 -1197.12,5585.67 -1163.79,5569 -1180.45,5602.33 -1163.79,5635.67 -1197.12,5619 -1230.45,5635.67 -1213.79,5602.33 -1230.45,5569 ; -1230.45,5719 -1163.79,5719 -1163.79,5785.67 -1230.45,5785.67 -1230.45,5719 ; -1230.45,6085.67 -1163.79,6085.67 -1197.12,6019 -1230.45,6085.67 ; -1230.45,6202.33 -1197.12,6169 -1163.79,6202.33 -1197.12,6235.67 -1230.45,6202.33 ; -1230.45,6319 -1230.45,6335.67 -1213.79,6352.33 -1230.45,6369 -1230.45,6385.67 -1213.79,6385.67 -1197.12,6369 -1180.45,6385.67 -1163.79,6385.67 -1163.79,6369 -1180.45,6352.33 -1163.79,6335.67 -1163.79,6319 -1180.45,6319 -1197.12,6335.67 -1213.79,6319 -1230.45,6319
  lines w12: -1290.24,5074 4606.15,5074 ; -1290.24,6424 4606.15,6424 ; -739.37,4924 -739.37,6574 ; -89.54,4924 -89.54,6574 ; 1050.12,4924 1050.12,6574 ; 1556,4924 1556,6574 ; 2289.8,4924 2289.8,6574 ; 3479.46,4924 3479.46,6574 ; -1290.24,4924 4606.15,4924 4606.15,6574 -1290.24,6574 -1290.24,4924
  text "Symbol" at -1200.24,6469 h72
  text "Count" at -694.37,6469 h72
  text "Hole Size" at -44.54,6469 h72
  text "Plated" at 1095.12,6469 h72
  text "Hole Type" at 1601,6469 h72
  text "Drill Layer Pair" at 2334.8,6469 h72
  text "Hole Tolerance" at 3524.46,6469 h72
  text "18" at -694.37,6319 h60
  text "7.87mil (0.200mm)" at -44.54,6319 h60
  text "PTH" at 1095.12,6319 h60
  text "Round" at 1601,6319 h60
  text "Top Layer - Bottom" at 2334.8,6319 h60
  text "971" at -694.37,6169 h60
  text "8.00mil (0.203mm)" at -44.54,6169 h60
  text "PTH" at 1095.12,6169 h60
  text "Round" at 1601,6169 h60
  text "Top Layer - Bottom" at 2334.8,6169 h60
  text "28" at -694.37,6019 h60
  text "15.75mil (0.400mm)" at -44.54,6019 h60
  text "PTH" at 1095.12,6019 h60
  text "Round" at 1601,6019 h60
  text "Top Layer - Bottom" at 2334.8,6019 h60
  text "8" at -694.37,5869 h60
  text "23.62mil (0.600mm)" at -44.54,5869 h60
  text "PTH" at 1095.12,5869 h60
  text "Slot" at 1601,5869 h60
  text "Top Layer - Bottom" at 2334.8,5869 h60
  text "11" at -694.37,5719 h60
  text "25.00mil (0.635mm)" at -44.54,5719 h60
  text "PTH" at 1095.12,5719 h60
  text "Round" at 1601,5719 h60
  text "Top Layer - Bottom" at 2334.8,5719 h60
  text "10" at -694.37,5569 h60
  text "35.04mil (0.890mm)" at -44.54,5569 h60
  text "PTH" at 1095.12,5569 h60
  text "Round" at 1601,5569 h60
  text "Top Layer - Bottom" at 2334.8,5569 h60
  text "2" at -694.37,5419 h60
  text "35.43mil (0.900mm)" at -44.54,5419 h60
  text "NPTH" at 1095.12,5419 h60
  text "Round" at 1601,5419 h60
  text "Top Layer - Bottom" at 2334.8,5419 h60
  text "2" at -694.37,5269 h60
  text "45.00mil (1.143mm)" at -44.54,5269 h60
  text "PTH" at 1095.12,5269 h60
  text "Round" at 1601,5269 h60
  text "Top Layer - Bottom" at 2334.8,5269 h60
  text "4" at -694.37,5119 h60
  text "110.24mil (2.800mm)" at -44.54,5119 h60
  text "NPTH" at 1095.12,5119 h60
  text "Round" at 1601,5119 h60
  text "Top Layer - Bottom" at 2334.8,5119 h60
  text "+1.97mil/-1.18mil" at 3524.46,5119 h60
  text "1054 Total" at -694.37,4969 h60
  text "Slot definitions :" at -1200.24,4824.03 h60
  text "Routed Path Length" at -167.55,4824.03 h60
  text "= Calculated from tool start centre position to tool end centre position." at 935.11,4824.03 h60
  text "Hole Length" at -167.55,4724.05 h60
  text "= Routed Path Length + Tool Size = Slot length as defined in the PCB layout" at 525.25,4724.05 h60
  text ".Layer_Name" at -765.05,-899.49 h60
M17 Embedded Cavity:
  text ".Layer_Name" at -765.05,-899.49 h60
M18 Embedded Assembly:
  text ".Layer_Name" at -765.05,-899.49 h60
M19 Embedded Keepout:
  text ".Layer_Name" at -765.05,-899.49 h60

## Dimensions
-1342.05,-440.99 to -342.05,-440.99 on M2 Board Dimensions
1715.83,1524.27 to 1713.83,3359.27 on M2 Board Dimensions
1714.83,3400.25 to 5878.81,3400.25 on M2 Board Dimensions
5879.8,3363.27 to 5817.38,1050.29 on M2 Board Dimensions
